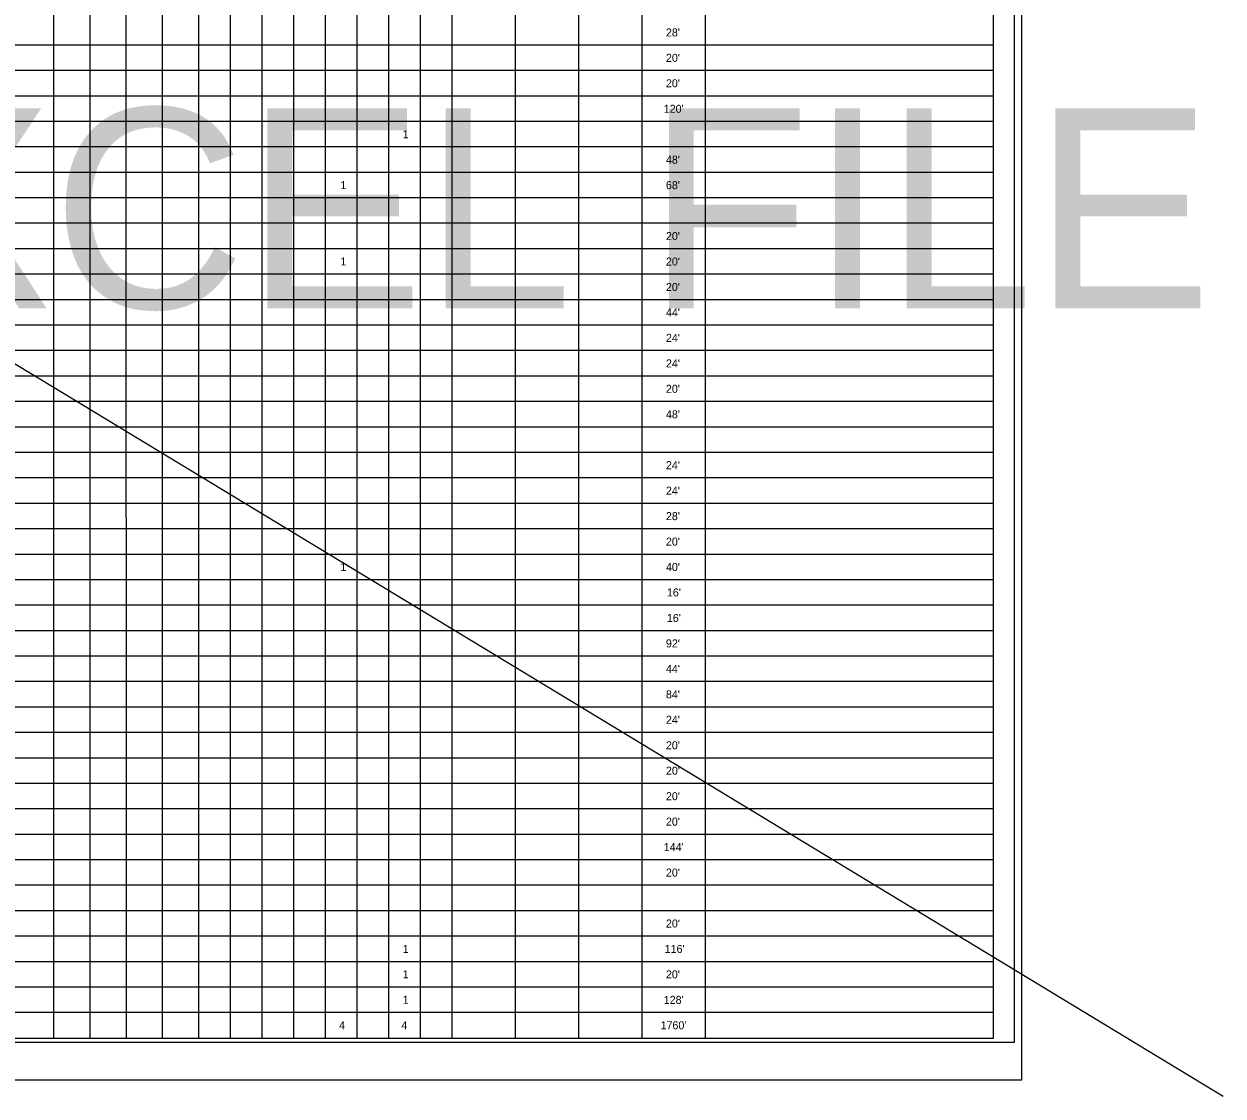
# Model space of a CAD drawing. Extents: x 1912359 to 1914224, y 232944 to 234289.
# Drawn here: x 1913505 to 1914224, y 232978 to 233621 of the extents above; entities that cross this region are included whole.
import ezdxf

# ---------------------------------------------------------------- set-up
doc = ezdxf.new("R2010")
doc.units = 0
for name, color, linetype in [('Old_Level_3', 7, 'Continuous'), ('Sheet Cutting Line CELL', 7, 'Continuous'), ('Sheet Pipe Summary CELL', 7, 'Continuous'), ('Sheet Pipe Summary Grid CELL', 7, 'Continuous'), ('Sheet Plot Border Inside CELL', 7, 'Continuous'), ('Sheet Plot Border Outside CELL', 7, 'Continuous'), ('Sheet Summary Combination CELL', 7, 'Continuous')]:
    doc.layers.add(name, color=color, linetype=linetype)

msp = doc.modelspace()

# ---------------------------------------------------------------- linework, layer by layer
at = {"layer": 'Old_Level_3'}
msp.add_line((1912359.16, 234107.85), (1914224.06, 232978.02), dxfattribs=at)
at = {"layer": 'Sheet Cutting Line CELL'}
msp.add_line((1912419.42, 232987.79), (1914103.42, 232987.79), dxfattribs=at)
msp.add_line((1912419.42, 232987.79), (1914103.42, 232987.79), dxfattribs=at)
at = {"layer": 'Sheet Pipe Summary CELL'}
msp.add_lwpolyline([(1914086.42, 234062.79), (1912586.42, 234062.79), (1912586.42, 233012.79), (1914086.42, 233012.79)], close=True, dxfattribs=at)
at = {"layer": 'Sheet Pipe Summary Grid CELL'}
for p, q in [((1913522.74, 233012.85), (1913522.69, 233966.65)), ((1913609.69, 233012.85), (1913609.64, 233966.65)), ((1913647.69, 233012.71), (1913647.64, 233966.66)), ((1913666.69, 233012.71), (1913666.64, 233966.66)), ((1913685.69, 233012.71), (1913685.64, 233966.66)), ((1913704.69, 233012.71), (1913704.64, 233966.66)), ((1913723.69, 233012.71), (1913723.64, 233966.66)), ((1913742.69, 233012.71), (1913742.64, 233966.66)), ((1913761.69, 233012.71), (1913761.64, 233966.66)), ((1913799.69, 233012.71), (1913799.64, 233966.66)), ((1913799.69, 233012.71), (1913799.64, 233966.66)), ((1913837.69, 233012.72), (1913837.64, 233966.67)), ((1913837.69, 233012.72), (1913837.64, 233966.67)), ((1913875.69, 233012.72), (1913875.64, 233966.67)), ((1913875.69, 233012.72), (1913875.64, 233966.67)), ((1913913.69, 233012.72), (1913913.64, 233966.67)), ((1913913.69, 233012.72), (1913913.64, 233966.67)), ((1913628.69, 233012.71), (1913628.65, 233875.95)), ((1913544.49, 233012.85), (1913544.39, 233790.6)), ((1913566.19, 233012.85), (1913566.14, 233790.6)), ((1913587.94, 233012.85), (1913587.94, 233790.6)), ((1914086.42, 233608.29), (1912586.42, 233608.29)), ((1914086.42, 233593.04), (1912586.42, 233593.04)), ((1914086.42, 233577.79), (1912586.42, 233577.79)), ((1914086.42, 233562.49), (1912586.42, 233562.49)), ((1914086.42, 233547.24), (1912586.42, 233547.24)), ((1914086.42, 233531.94), (1912586.42, 233531.94)), ((1914086.42, 233516.69), (1912586.42, 233516.69)), ((1914086.42, 233501.44), (1912586.42, 233501.44)), ((1914086.42, 233486.14), (1912586.42, 233486.14)), ((1914086.42, 233470.89), (1912586.42, 233470.89)), ((1914086.42, 233455.59), (1912586.42, 233455.59)), ((1914086.42, 233440.34), (1912586.42, 233440.34)), ((1914086.42, 233425.09), (1912586.42, 233425.09)), ((1914086.42, 233409.79), (1912586.42, 233409.79)), ((1914086.42, 233394.54), (1912586.42, 233394.54)), ((1914086.42, 233379.24), (1912586.42, 233379.24)), ((1914086.42, 233363.99), (1912586.42, 233363.99)), ((1914086.42, 233348.74), (1912586.42, 233348.74)), ((1914086.42, 233333.44), (1912586.42, 233333.44)), ((1914086.42, 233318.19), (1912586.42, 233318.19)), ((1914086.42, 233302.89), (1912586.42, 233302.89)), ((1914086.42, 233287.64), (1912586.42, 233287.64)), ((1914086.42, 233272.39), (1912586.42, 233272.39)), ((1914086.42, 233257.09), (1912586.42, 233257.09)), ((1914086.42, 233241.84), (1912586.42, 233241.84)), ((1914086.42, 233226.54), (1912586.42, 233226.54)), ((1914086.42, 233211.29), (1912586.42, 233211.29)), ((1914086.42, 233196.04), (1912586.42, 233196.04)), ((1914086.42, 233180.74), (1912586.42, 233180.74)), ((1914086.42, 233165.49), (1912586.42, 233165.49)), ((1914086.42, 233150.19), (1912586.42, 233150.19)), ((1914086.42, 233134.94), (1912586.42, 233134.94)), ((1914086.42, 233119.69), (1912586.42, 233119.69)), ((1914086.42, 233104.39), (1912586.42, 233104.39)), ((1914086.42, 233089.14), (1912586.42, 233089.14)), ((1914086.42, 233073.84), (1912586.42, 233073.84)), ((1914086.42, 233058.59), (1912586.42, 233058.59)), ((1914086.42, 233043.34), (1912586.42, 233043.34)), ((1914086.42, 233028.04), (1912586.42, 233028.04))]:
    msp.add_line(p, q, dxfattribs=at)
at = {"layer": 'Sheet Plot Border Inside CELL'}
msp.add_lwpolyline([(1912432.42, 233010.24), (1914098.92, 233010.24), (1914098.92, 234065.34), (1912432.42, 234065.34)], close=True, dxfattribs=at)
at = {"layer": 'Sheet Plot Border Outside CELL'}
msp.add_lwpolyline([(1912419.42, 232987.79), (1914103.42, 232987.79), (1914103.42, 234087.79), (1912419.42, 234087.79)], close=True, dxfattribs=at)

# ---------------------------------------------------------------- texts
at = {"layer": 'Sheet Summary Combination CELL'}
for s, height, p in [("28'", 4.8, (1913889.87, 233613.54)), ("20'", 4.8, (1913889.87, 233598.29)), ("20'", 4.8, (1913889.87, 233583.04)), ('SEE DDS EXCEL FILE', 120, (1912558.6, 233450.45)), ("120'", 4.8, (1913888.55, 233567.74)), ('1', 4.8, (1913731.96, 233552.51)), ("48'", 4.8, (1913889.87, 233537.19)), ('1', 4.8, (1913694.61, 233521.95)), ("68'", 4.8, (1913889.87, 233521.94)), ("20'", 4.8, (1913889.87, 233491.39)), ('1', 4.8, (1913694.61, 233476.15)), ("20'", 4.8, (1913889.87, 233476.14)), ("20'", 4.8, (1913889.87, 233460.84)), ("44'", 4.8, (1913889.87, 233445.59)), ("24'", 4.8, (1913889.87, 233430.34)), ("24'", 4.8, (1913889.87, 233415.04)), ("20'", 4.8, (1913889.87, 233399.79)), ("48'", 4.8, (1913889.87, 233384.49)), ("24'", 4.8, (1913889.87, 233353.99)), ("24'", 4.8, (1913889.87, 233338.69)), ("28'", 4.8, (1913889.87, 233323.44)), ("20'", 4.8, (1913889.87, 233308.14)), ('1', 4.8, (1913694.61, 233292.9)), ("40'", 4.8, (1913889.87, 233292.89)), ("16'", 4.8, (1913890.44, 233277.64)), ("16'", 4.8, (1913890.44, 233262.34)), ("92'", 4.8, (1913889.87, 233247.09)), ("44'", 4.8, (1913889.87, 233231.79)), ("84'", 4.8, (1913889.87, 233216.54)), ("24'", 4.8, (1913889.87, 233201.29)), ("20'", 4.8, (1913889.87, 233185.99)), ("20'", 4.8, (1913889.87, 233170.74)), ("20'", 4.8, (1913889.87, 233155.44)), ("20'", 4.8, (1913889.87, 233140.19)), ("144'", 4.8, (1913888.55, 233124.94)), ("20'", 4.8, (1913889.87, 233109.64)), ("20'", 4.8, (1913889.87, 233079.09)), ('1', 4.8, (1913731.96, 233063.86)), ("116'", 4.8, (1913889.12, 233063.84)), ('1', 4.8, (1913731.96, 233048.61)), ("20'", 4.8, (1913889.87, 233048.59)), ('1', 4.8, (1913731.96, 233033.31)), ("128'", 4.8, (1913888.55, 233033.29)), ('4', 4.8, (1913693.8, 233018.05)), ('4', 4.8, (1913731.15, 233018.06)), ("1760'", 4.8, (1913886.65, 233018.04))]:
    msp.add_text(s, height=height, dxfattribs=at).set_placement(p)

doc.saveas('drawing.dxf')
